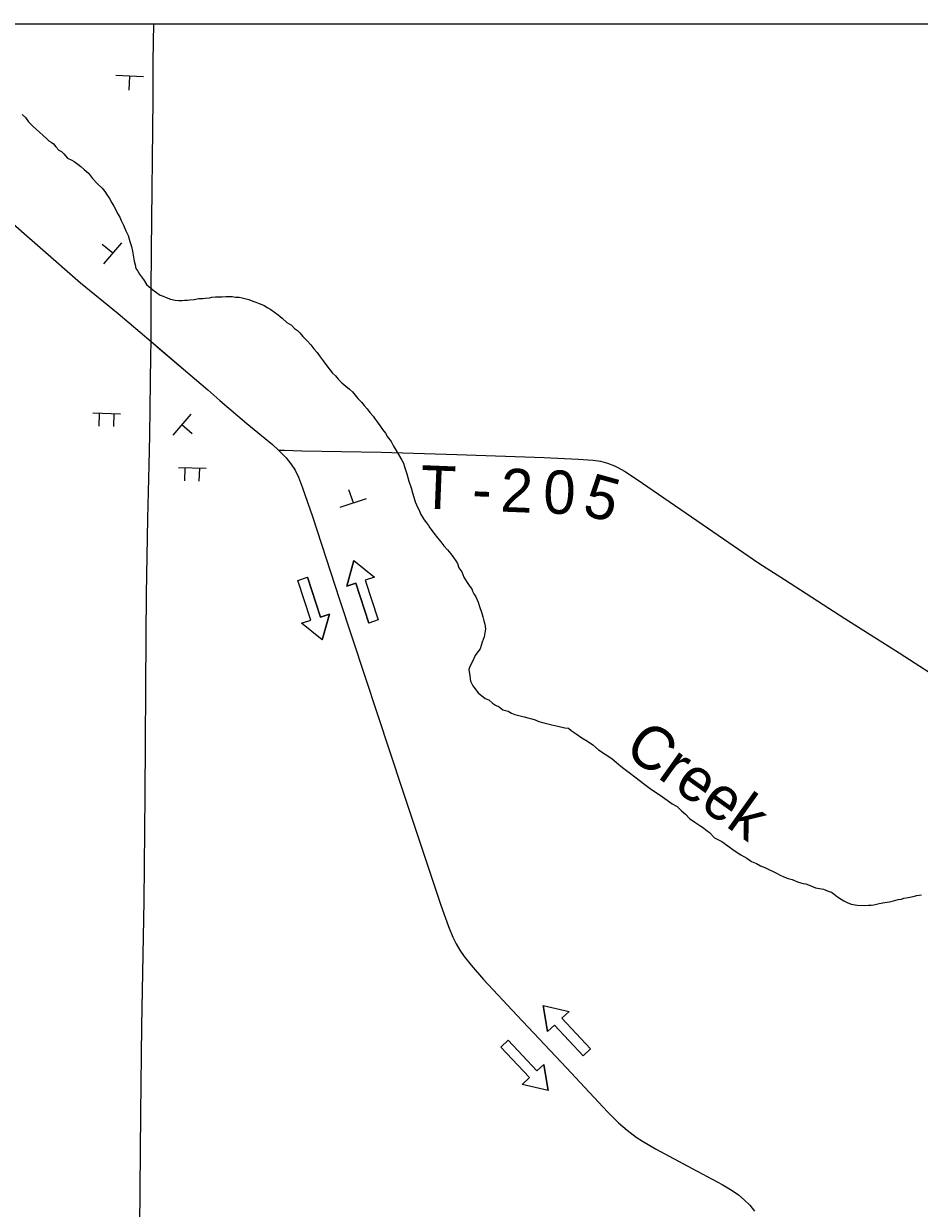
# Model space of a CAD drawing. Extents: x 1 to 1675, y -2 to 1113.
# Drawn here: x 1656.36 to 1661.53, y 1098.56 to 1105.4 of the extents above; entities that cross this region are included whole.
import ezdxf

# ---------------------------------------------------------------- set-up
doc = ezdxf.new("R2010")
doc.units = 0
for name, color, linetype in [('GM_X_Minor_River_Text', 7, 'Continuous'), ('GM_X_State_Route', 7, 'Continuous'), ('GM_X_Township_Road_Text', 7, 'Continuous'), ('SC_Scratch1', 7, 'Continuous'), ('SH_Data', 7, 'Continuous'), ('SH_Text', 7, 'Continuous'), ('SN_P_Signs', 7, 'Continuous'), ('SN_P_Text', 7, 'Continuous')]:
    doc.layers.add(name, color=color, linetype=linetype)

msp = doc.modelspace()

# ---------------------------------------------------------------- linework, layer by layer
at = {"layer": 'GM_X_State_Route'}
for points in [[(1654.9357, 1105.4005), (1655.6768, 1104.7676), (1655.9427, 1104.5405), (1656.0756, 1104.4269), (1656.2343, 1104.2977), (1656.6852, 1103.9049), (1656.9037, 1103.7272), (1657.0942, 1103.5646), (1657.1425, 1103.5234)], [(1654.9357, 1105.4005), (1655.6768, 1104.7676), (1655.9427, 1104.5405), (1656.0756, 1104.4269), (1656.2343, 1104.2977), (1656.6852, 1103.9049), (1656.9037, 1103.7272), (1657.0942, 1103.5646), (1657.1425, 1103.5234)], [(1657.1425, 1103.5234), (1657.3052, 1103.3845), (1657.422, 1103.2855), (1657.4917, 1103.2249), (1657.6472, 1103.0924), (1657.7944, 1102.9707), (1657.8299, 1102.9385), (1657.8734, 1102.8938), (1657.901, 1102.859), (1657.9251, 1102.8217), (1657.9451, 1102.7821), (1657.9692, 1102.7204), (1658.0255, 1102.5544), (1658.1821, 1102.0759), (1658.547, 1100.9745), (1658.7669, 1100.3094), (1658.8112, 1100.1861), (1658.8364, 1100.1258), (1658.8558, 1100.0871), (1658.8777, 1100.0498), (1658.902, 1100.0139), (1658.9421, 1099.9626), (1659.015, 1099.8813), (1659.2096, 1099.6737), (1659.4941, 1099.3702), (1659.7329, 1099.1141), (1659.7949, 1099.0528), (1659.8441, 1099.01), (1659.8961, 1098.9708), (1659.9323, 1098.947), (1660.0079, 1098.9036), (1660.2199, 1098.7896), (1660.3938, 1098.6964), (1660.4506, 1098.6625), (1660.4869, 1098.6371), (1660.5209, 1098.6089), (1660.552, 1098.5772), (1660.5797, 1098.5427)]]:
    msp.add_lwpolyline(points, dxfattribs=at)
at = {"layer": 'SC_Scratch1'}
for points in [[(1656.3487, 1104.8769), (1656.3673, 1104.8579), (1656.3857, 1104.8336), (1656.4096, 1104.8091), (1656.4308, 1104.7901), (1656.4494, 1104.7738), (1656.4707, 1104.7548), (1656.4893, 1104.7384), (1656.5025, 1104.7249), (1656.5159, 1104.7167), (1656.5291, 1104.7058), (1656.5424, 1104.6895), (1656.5609, 1104.6705), (1656.5769, 1104.6623), (1656.5902, 1104.6487), (1656.6114, 1104.6243), (1656.6354, 1104.6133), (1656.6487, 1104.6051), (1656.67, 1104.5887), (1656.6886, 1104.5751), (1656.7072, 1104.5588), (1656.7311, 1104.5371), (1656.7549, 1104.5073), (1656.7841, 1104.4748), (1656.8106, 1104.4503), (1656.8265, 1104.4313), (1656.8396, 1104.4097), (1656.8528, 1104.3908), (1656.8659, 1104.3665), (1656.8791, 1104.3476), (1656.887, 1104.3287), (1656.9001, 1104.3045), (1656.9132, 1104.2829), (1656.9211, 1104.264), (1656.9341, 1104.2371), (1656.9472, 1104.2047), (1656.9603, 1104.1778), (1656.9705, 1104.1428), (1656.9809, 1104.1132), (1656.986, 1104.0864), (1656.996, 1104.03), (1657.0011, 1104.0085), (1657.0062, 1103.987), (1657.0167, 1103.9708), (1657.0273, 1103.9546), (1657.0431, 1103.9303), (1657.0537, 1103.9167), (1657.0668, 1103.8951), (1657.0934, 1103.8707), (1657.112, 1103.857), (1657.1253, 1103.8488), (1657.1466, 1103.8325), (1657.1626, 1103.8269), (1657.1813, 1103.8186), (1657.2054, 1103.8103), (1657.2322, 1103.8046), (1657.2536, 1103.8016), (1657.2724, 1103.8014), (1657.2859, 1103.8039), (1657.302, 1103.8037), (1657.3181, 1103.8061), (1657.3423, 1103.8085), (1657.3692, 1103.8135), (1657.3934, 1103.8132), (1657.4069, 1103.8157), (1657.4311, 1103.818), (1657.4445, 1103.8205), (1657.466, 1103.8229), (1657.4875, 1103.8227), (1657.5036, 1103.8224), (1657.5251, 1103.8248), (1657.5466, 1103.8245), (1657.5627, 1103.8243), (1657.5815, 1103.8214), (1657.603, 1103.8211), (1657.6191, 1103.8183), (1657.6592, 1103.807), (1657.6806, 1103.7987), (1657.6993, 1103.7931), (1657.718, 1103.7848), (1657.7341, 1103.7792), (1657.7474, 1103.7737), (1657.7687, 1103.76), (1657.7847, 1103.7491)], [(1657.7847, 1103.7491), (1657.806, 1103.7354), (1657.8273, 1103.7191), (1657.8512, 1103.7), (1657.8778, 1103.6756), (1657.9044, 1103.6591), (1657.923, 1103.6401), (1657.9389, 1103.6292), (1657.9522, 1103.6157), (1657.9707, 1103.594), (1657.9946, 1103.5696), (1658.0158, 1103.5452), (1658.0343, 1103.5235), (1658.0528, 1103.5018), (1658.0713, 1103.4775), (1658.0871, 1103.4532), (1658.103, 1103.4315), (1658.1215, 1103.4072), (1658.1426, 1103.3828), (1658.1585, 1103.3665), (1658.1744, 1103.3476), (1658.1956, 1103.3259), (1658.2196, 1103.3068), (1658.2408, 1103.2904), (1658.2567, 1103.2742), (1658.2726, 1103.2552), (1658.2885, 1103.2362), (1658.3097, 1103.2145), (1658.3256, 1103.1956), (1658.3415, 1103.1766), (1658.3573, 1103.155), (1658.3758, 1103.1333), (1658.389, 1103.1171), (1658.3996, 1103.1009), (1658.4154, 1103.0792), (1658.4313, 1103.0576), (1658.4471, 1103.0359), (1658.4603, 1103.0143), (1658.4814, 1102.9873), (1658.4945, 1102.9603), (1658.5103, 1102.936), (1658.5418, 1102.8793), (1658.5523, 1102.8631), (1658.5601, 1102.8362), (1658.5704, 1102.8013), (1658.5833, 1102.7583), (1658.5962, 1102.7206), (1658.6039, 1102.691), (1658.6117, 1102.6668), (1658.6194, 1102.6399), (1658.6272, 1102.6211), (1658.635, 1102.6049), (1658.6429, 1102.5914), (1658.6507, 1102.5699), (1658.6612, 1102.551), (1658.6718, 1102.5348), (1658.685, 1102.5185), (1658.6955, 1102.5023), (1658.7034, 1102.4888), (1658.7166, 1102.4726), (1658.7272, 1102.459), (1658.7483, 1102.432), (1658.7668, 1102.4076), (1658.7854, 1102.3859), (1658.8065, 1102.3616), (1658.8251, 1102.3399), (1658.8409, 1102.3183), (1658.8541, 1102.2993), (1658.8646, 1102.2831), (1658.8724, 1102.2589), (1658.8882, 1102.2346), (1658.9013, 1102.205), (1658.9196, 1102.1726), (1658.9355, 1102.1509), (1658.9461, 1102.1374), (1658.9513, 1102.1239), (1658.9591, 1102.1078), (1658.9696, 1102.0916), (1658.9749, 1102.0781), (1658.9827, 1102.0593), (1658.9904, 1102.035), (1659.0034, 1102.0027), (1659.0111, 1101.9758), (1659.0162, 1101.9517), (1659.0213, 1101.9328), (1659.0264, 1101.906), (1659.0178, 1101.8606), (1659.0066, 1101.8286), (1658.9954, 1101.7912), (1658.9763, 1101.7647), (1658.9654, 1101.7514), (1658.9488, 1101.7141), (1658.935, 1101.6875), (1658.9294, 1101.6715), (1658.9343, 1101.634), (1658.9393, 1101.6044), (1658.9524, 1101.5775), (1658.9841, 1101.5369), (1659.024, 1101.5042), (1659.0454, 1101.4959), (1659.0666, 1101.4769)], [(1659.0666, 1101.4769), (1659.0826, 1101.4659), (1659.104, 1101.4549), (1659.1252, 1101.4386), (1659.1574, 1101.4301), (1659.176, 1101.4192), (1659.1947, 1101.4109), (1659.2483, 1101.3968), (1659.2697, 1101.3912), (1659.2938, 1101.3855), (1659.3125, 1101.3799), (1659.3339, 1101.3716), (1659.3633, 1101.3631), (1659.4088, 1101.3518), (1659.4436, 1101.3433), (1659.4838, 1101.3348), (1659.5053, 1101.3318), (1659.5212, 1101.3182), (1659.5505, 1101.2991), (1659.5824, 1101.2772), (1659.6144, 1101.2581), (1659.6464, 1101.2362), (1659.6782, 1101.2063), (1659.7235, 1101.179), (1659.7555, 1101.1571), (1659.7847, 1101.1326), (1659.8166, 1101.1054), (1659.8565, 1101.0754), (1659.8964, 1101.0454), (1659.939, 1101.0127), (1659.9842, 1100.9773), (1660.0348, 1100.9445), (1660.0747, 1100.9172), (1660.104, 1100.8954), (1660.1333, 1100.8789), (1660.1572, 1100.8545), (1660.1811, 1100.8355), (1660.205, 1100.811), (1660.2343, 1100.7892), (1660.2636, 1100.7701), (1660.2849, 1100.7564), (1660.2982, 1100.7455), (1660.3194, 1100.7292), (1660.3486, 1100.6993), (1660.3913, 1100.6773), (1660.4259, 1100.6528), (1660.4632, 1100.6255), (1660.5004, 1100.6009), (1660.5351, 1100.5817), (1660.5617, 1100.5626), (1660.5911, 1100.5515), (1660.6151, 1100.5378), (1660.6391, 1100.5268), (1660.7113, 1100.4937), (1660.7246, 1100.4855), (1660.7486, 1100.4744), (1660.7753, 1100.4634), (1660.7967, 1100.4577), (1660.8101, 1100.4522), (1660.8288, 1100.4439), (1660.8475, 1100.4383), (1660.8609, 1100.4355), (1660.877, 1100.4326), (1660.901, 1100.4242), (1660.9331, 1100.4104), (1660.9786, 1100.4018), (1661.0054, 1100.3907), (1661.0241, 1100.3851), (1661.0401, 1100.3742), (1661.0587, 1100.3579), (1661.08, 1100.3442), (1661.096, 1100.3359), (1661.1146, 1100.325), (1661.1387, 1100.3166), (1661.1735, 1100.3108), (1661.2138, 1100.3076), (1661.238, 1100.31), (1661.2541, 1100.3098), (1661.2703, 1100.3122), (1661.2999, 1100.3199), (1661.3322, 1100.3248), (1661.3591, 1100.3298), (1661.3833, 1100.3349), (1661.4103, 1100.3425), (1661.4291, 1100.345), (1661.4426, 1100.3501), (1661.4668, 1100.3552), (1661.4964, 1100.3602), (1661.518, 1100.3652), (1661.5449, 1100.3703)]]:
    msp.add_lwpolyline(points, dxfattribs=at)
at = {"layer": 'SH_Data'}
msp.add_lwpolyline([(1653.1763, 1105.4005), (1672.2022, 1105.4005), (1672.2022, 1085.8005), (1653.1763, 1085.8005)], close=True, dxfattribs=at)
at = {"layer": 'SH_Text'}
for p, q in [((1658.2653, 1102.2998), (1658.224, 1102.1524)), ((1658.2653, 1102.2998), (1658.3853, 1102.2048)), ((1657.9417, 1102.1857), (1657.9969, 1102.2036)), ((1658.0165, 1101.9555), (1657.9417, 1102.1857)), ((1658.0717, 1101.9734), (1657.9969, 1102.2036)), ((1658.3853, 1102.2048), (1658.3311, 1102.1872)), ((1658.3311, 1102.1872), (1658.4059, 1101.957)), ((1658.224, 1102.1524), (1658.2759, 1102.1692)), ((1658.2759, 1102.1692), (1658.3507, 1101.9391)), ((1658.1236, 1101.9903), (1658.0717, 1101.9734)), ((1658.0824, 1101.8428), (1658.1236, 1101.9903)), ((1657.9623, 1101.9379), (1658.0165, 1101.9555)), ((1658.0824, 1101.8428), (1657.9623, 1101.9379)), ((1658.4059, 1101.957), (1658.3507, 1101.9391)), ((1659.3596, 1099.7311), (1659.5086, 1099.6958)), ((1659.3596, 1099.7311), (1659.3846, 1099.58)), ((1659.5086, 1099.6958), (1659.4669, 1099.6569)), ((1659.4669, 1099.6569), (1659.6321, 1099.4799)), ((1659.3846, 1099.58), (1659.4245, 1099.6173)), ((1659.4245, 1099.6173), (1659.5897, 1099.4404)), ((1659.1148, 1099.4908), (1659.1572, 1099.5304)), ((1659.3224, 1099.3535), (1659.1572, 1099.5304)), ((1659.28, 1099.3139), (1659.1148, 1099.4908)), ((1659.6321, 1099.4799), (1659.5897, 1099.4404)), ((1659.3623, 1099.3907), (1659.3224, 1099.3535)), ((1659.3873, 1099.2397), (1659.3623, 1099.3907)), ((1659.2383, 1099.275), (1659.28, 1099.3139)), ((1659.3873, 1099.2397), (1659.2383, 1099.275))]:
    msp.add_line(p, q, dxfattribs=at)
for points in [[(1657.0942, 1103.5646), (1657.3052, 1103.3845), (1657.422, 1103.2855), (1657.4917, 1103.2249), (1657.6472, 1103.0924), (1657.7944, 1102.9707), (1657.8299, 1102.9385), (1657.8734, 1102.8938), (1657.901, 1102.859), (1657.9251, 1102.8217), (1657.9451, 1102.7821), (1657.9692, 1102.7204), (1658.0255, 1102.5544), (1658.1821, 1102.0759), (1658.547, 1100.9745), (1658.7669, 1100.3094), (1658.8112, 1100.1861), (1658.8364, 1100.1258), (1658.8558, 1100.0871), (1658.8777, 1100.0498), (1658.902, 1100.0139), (1658.9421, 1099.9626), (1659.015, 1099.8813), (1659.2096, 1099.6737), (1659.4941, 1099.3702), (1659.7329, 1099.1141), (1659.7949, 1099.0528), (1659.8441, 1099.01), (1659.8961, 1098.9708), (1659.9323, 1098.947), (1660.0079, 1098.9036), (1660.2199, 1098.7896), (1660.3938, 1098.6964), (1660.4506, 1098.6625), (1660.4869, 1098.6371), (1660.5209, 1098.6089), (1660.552, 1098.5772), (1660.5797, 1098.5427)], [(1657.1425, 1103.5234), (1657.3052, 1103.3845), (1657.422, 1103.2855), (1657.4917, 1103.2249), (1657.6472, 1103.0924), (1657.7944, 1102.9707), (1657.8299, 1102.9385), (1657.8734, 1102.8938), (1657.901, 1102.859), (1657.9251, 1102.8217), (1657.9451, 1102.7821), (1657.9692, 1102.7204), (1658.0255, 1102.5544), (1658.1821, 1102.0759), (1658.547, 1100.9745), (1658.7669, 1100.3094), (1658.8112, 1100.1861), (1658.8364, 1100.1258), (1658.8558, 1100.0871), (1658.8777, 1100.0498), (1658.902, 1100.0139), (1658.9421, 1099.9626), (1659.015, 1099.8813), (1659.2096, 1099.6737), (1659.4941, 1099.3702), (1659.7329, 1099.1141), (1659.7949, 1099.0528), (1659.8441, 1099.01), (1659.8961, 1098.9708), (1659.9323, 1098.947), (1660.0079, 1098.9036), (1660.2199, 1098.7896), (1660.3938, 1098.6964), (1660.4506, 1098.6625), (1660.4869, 1098.6371), (1660.5209, 1098.6089), (1660.552, 1098.5772), (1660.5797, 1098.5427)]]:
    msp.add_lwpolyline(points, dxfattribs=at)
for points in [[(1658.3507, 1101.9391), (1658.2759, 1102.1693), (1658.224, 1102.1524), (1658.2652, 1102.2998), (1658.3853, 1102.2048), (1658.3311, 1102.1872), (1658.4059, 1101.957)], [(1657.9969, 1102.2036), (1658.0717, 1101.9734), (1658.1236, 1101.9903), (1658.0824, 1101.8428), (1657.9623, 1101.9379), (1658.0165, 1101.9555), (1657.9417, 1102.1857)], [(1659.5897, 1099.4404), (1659.4245, 1099.6173), (1659.3846, 1099.58), (1659.3596, 1099.7311), (1659.5086, 1099.6958), (1659.4669, 1099.6569), (1659.6321, 1099.48)], [(1659.1572, 1099.5304), (1659.3224, 1099.3535), (1659.3623, 1099.3907), (1659.3873, 1099.2397), (1659.2383, 1099.275), (1659.28, 1099.3139), (1659.1148, 1099.4908)]]:
    msp.add_lwpolyline(points, close=True, dxfattribs=at)
at = {"layer": 'SN_P_Signs'}
for p, q in [((1657.0492, 1105.0933), (1656.8894, 1105.1015)), ((1656.9693, 1105.0974), (1656.9652, 1105.0175)), ((1656.8725, 1104.0746), (1656.8114, 1104.1263)), ((1656.8207, 1104.0135), (1656.9242, 1104.1356)), ((1656.7574, 1103.1531), (1656.9171, 1103.1479)), ((1656.7943, 1103.1519), (1656.7919, 1103.0766)), ((1656.8786, 1103.1492), (1656.8762, 1103.0739)), ((1657.3224, 1103.1459), (1657.2185, 1103.0243)), ((1657.2704, 1103.0851), (1657.3313, 1103.0331)), ((1657.2514, 1102.8379), (1657.411, 1102.8328)), ((1657.2882, 1102.8367), (1657.2858, 1102.7614)), ((1657.3725, 1102.834), (1657.3701, 1102.7587)), ((1658.1869, 1102.6077), (1658.3384, 1102.659)), ((1658.2627, 1102.6333), (1658.237, 1102.7091))]:
    msp.add_line(p, q, dxfattribs=at)
for points in [[(1657.0942, 1103.5646), (1657.0939, 1103.8519), (1657.0962, 1104.0925), (1657.1054, 1104.9672), (1657.1056, 1105.1858), (1657.11, 1105.4005)], [(1657.0942, 1103.5646), (1657.0939, 1103.8519), (1657.0962, 1104.0925), (1657.1054, 1104.9672), (1657.1056, 1105.1858), (1657.11, 1105.4005)], [(1657.0277, 1098.4513), (1657.0348, 1099.1076), (1657.0408, 1099.6108), (1657.0533, 1100.333), (1657.0588, 1100.9459), (1657.0648, 1101.8653), (1657.0676, 1102.106), (1657.0741, 1102.5438), (1657.0826, 1102.8501), (1657.0857, 1103.025), (1657.0895, 1103.3315), (1657.0926, 1103.4842), (1657.0942, 1103.5646)], [(1657.0277, 1098.4513), (1657.0348, 1099.1076), (1657.0408, 1099.6108), (1657.0533, 1100.333), (1657.0588, 1100.9459), (1657.0648, 1101.8653), (1657.0676, 1102.106), (1657.0741, 1102.5438), (1657.0826, 1102.8501), (1657.0857, 1103.025), (1657.0895, 1103.3315), (1657.0926, 1103.4842), (1657.0942, 1103.5646)]]:
    msp.add_lwpolyline(points, dxfattribs=at)
at = {"layer": 'SN_P_Text'}
msp.add_lwpolyline([(1657.8299, 1102.9385), (1657.8641, 1102.9371), (1657.964, 1102.933), (1658.4235, 1102.9263), (1658.8608, 1102.9135), (1659.3637, 1102.8945), (1659.5605, 1102.8864), (1659.6473, 1102.8799), (1659.6898, 1102.8736), (1659.7314, 1102.863), (1659.7714, 1102.8473), (1659.7906, 1102.8377), (1659.8284, 1102.8162), (1659.9017, 1102.7689), (1660.3702, 1102.4462), (1660.6052, 1102.2857), (1660.7524, 1102.1908), (1661.1022, 1101.9662), (1661.4164, 1101.767), (1661.7478, 1101.5543)], dxfattribs=at)
msp.add_lwpolyline([(1657.8299, 1102.9385), (1657.8641, 1102.9371), (1657.964, 1102.933), (1658.4235, 1102.9263), (1658.8608, 1102.9135), (1659.3637, 1102.8945), (1659.5605, 1102.8864), (1659.6473, 1102.8799), (1659.6898, 1102.8736), (1659.7314, 1102.863), (1659.7714, 1102.8473), (1659.7906, 1102.8377), (1659.8284, 1102.8162), (1659.9017, 1102.7689), (1660.3702, 1102.4462), (1660.6052, 1102.2857), (1660.7524, 1102.1908), (1661.1022, 1101.9662), (1661.4164, 1101.767), (1661.7478, 1101.5543)], dxfattribs=at)

# ---------------------------------------------------------------- texts
at = {"layer": 'GM_X_Minor_River_Text'}
msp.add_text('Creek', height=0.25, rotation=324.54134, dxfattribs=at).set_placement((1659.8176, 1101.1888))
at = {"layer": 'GM_X_Township_Road_Text'}
for s, rotation, p in [('T', 357.75804, (1658.6463, 1102.6014)), ('2', 357.76467, (1659.1094, 1102.5833)), ('0', 357.78021, (1659.3557, 1102.5736)), ('5', 344.40486, (1659.5776, 1102.5679)), ('-', 357.76214, (1658.9453, 1102.5897))]:
    msp.add_text(s, height=0.25, rotation=rotation, dxfattribs=at).set_placement(p)

doc.saveas('drawing.dxf')
